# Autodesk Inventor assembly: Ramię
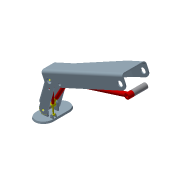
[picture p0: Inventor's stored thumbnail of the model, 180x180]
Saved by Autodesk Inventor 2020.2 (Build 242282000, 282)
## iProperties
Created: 2006-08
Part Number: Ramię
Document SubType Name: Assembly
Designer: F.Stasiak
Manager: www.cadconsulting.pl
Company: Fabian Stasiak CAD Consulting
Author: F.Stasiak
Subject: Zbiór ćwiczeń. Autodesk Inventor 2020. Kurs podstawowy
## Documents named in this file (9)
- C:\2020_Kurs_podstawowy\R6 Zespoły\Lustro\Ramię.iam
- C:\2020_Kurs_podstawowy\R6 Zespoły\Lustro\Ramię1.ipt
- C:\2020_Kurs_podstawowy\R6 Zespoły\Lustro\Ramię2.ipt
- C:\2020_Kurs_podstawowy\R6 Zespoły\Lustro\Tuleja1.ipt
- C:\2020_Kurs_podstawowy\R6 Zespoły\Lustro\Tuleja3.ipt
- C:\2020_Kurs_podstawowy\R6 Zespoły\Lustro\Stopa.ipt
- C:\2020_Kurs_podstawowy\R6 Zespoły\Lustro\SIL1.iam
- C:\2020_Kurs_podstawowy\R6 Zespoły\Lustro\SIL2.iam
- C:\2020_Kurs_podstawowy\R6 Zespoły\Lustro\SIL3.iam
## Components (8 placed, 8 different names)
1. Ramię1:1
2. Ramię2:1 — Zestawiający:1
3. Tuleja1:1 — Wstaw:9
4. Tuleja3:1
5. Stopa:1
6. SIL1:1 [sub-assembly] — Wstaw:9
7. SIL2:1 [sub-assembly]
8. SIL3:1 [sub-assembly] — Zestawiający:1
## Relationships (2: Mate 1, Insert 1)
- Zestawiający:1 [Mate]: Ramię2:1 ↔ SIL3:1
- Wstaw:9 [Insert]: Tuleja1:1 ↔ SIL1:1
## Named parameters: d0_d5 = 0
